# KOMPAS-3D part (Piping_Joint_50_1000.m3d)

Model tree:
1. Plane XY
2. Plane ZX
3. Plane ZY
4. X Axis
5. Y Axis
6. Z Axis
7. Origin
8. Sketch:1
9. Extrude:1  (labels: На расстояние 1; На расстояние 2)
     Толщина стенки 1 = 1; Толщина стенки 2 = 1; Расстояние 1 = 2; Расстояние 2 = 10
10. Sketch:2
11. Attachment Point:1
12. Attachment Point:2  (labels: C:\Program Files\ASCON\KOMPAS-3D V10\Sys\graphic.lyt; Прокладка Dy 50)

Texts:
  Joint Dn 50
  Three Point Plane
  Plane at Angle
  Line and Point Plane
  Axis through Two Vertices
  Axis of Feature
  Axis of Conical Surface
  Axis through Edge
  Приклеить элемент выдавливания
  Приклеить элемент вращения
  Приклеить кинематический элемент
  Приклеить элемент по сечениям
  Trim by Surface
  Trim by Sketch
  Feature with No History
  Intersection Axis of Two Planes
  Two Line Plane
  Line and Face Plane
  Bend by line
  Hole in sheet body
  Cut in sheet body
  Point in CM
  Linear Dimension from Line to Point
  Surface Finish Symbol
  Geometric Tolerance Symbol
  Текст на чертеже
  Линия-выноска #1
  Линия-выноска #2
  Линия-выноска #3
  Отклонения формы и база
  Марка координационной оси
  Марка/позиционное обозначение с линией-выноской
  Марка/позиционное обозначение на линии
  Марка/позиционное обозначение без линии-выноски
  На расстояние 1
  На расстояние 2
  Прокладка Dy 50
